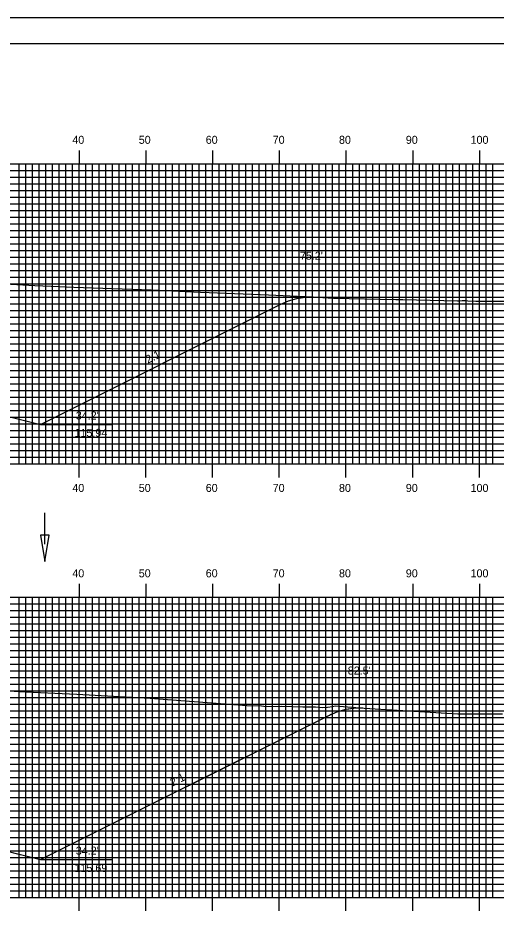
# Model space of a CAD drawing. Extents: x 1770448 to 1770792, y 442591 to 442811.
# Drawn here: x 1770644.9 to 1770716.5, y 442676.2 to 442810.5 of the extents above; entities that cross this region are included whole.
import ezdxf

# ---------------------------------------------------------------- set-up
doc = ezdxf.new("R2010")
doc.units = 0
for name, color, linetype in [('ANNOTATION', 7, 'Continuous'), ('BORDER', 7, 'Continuous'), ('D_Drainage_Ditch_Line', 7, 'Continuous'), ('D_Roadway_Centerline', 7, 'Continuous'), ('D_Roadway_SlopeLines', 7, 'Continuous'), ('D_Text_Standard', 7, 'Continuous'), ('H_V ANNOTATION', 7, 'Continuous'), ('MAJOR', 7, 'Continuous'), ('MINOR', 7, 'Continuous'), ('PDRAIN', 7, 'Continuous'), ('PLOT BOUNDARY', 7, 'Continuous'), ('S_Roadway_Centerline', 7, 'Continuous')]:
    doc.layers.add(name, color=color, linetype=linetype)

msp = doc.modelspace()

# ---------------------------------------------------------------- linework, layer by layer
at = {"layer": 'BORDER'}
msp.add_lwpolyline([(1770464.44, 442596.67), (1770784.44, 442596.67), (1770784.44, 442806.67), (1770464.44, 442806.67)], close=True, dxfattribs=at)
at = {"layer": 'D_Drainage_Ditch_Line'}
msp.add_line((1770648.9, 442731.66), (1770648.9, 442736.36), dxfattribs=at)
msp.add_lwpolyline([(1770649.56, 442732.97), (1770648.25, 442732.97), (1770648.9, 442729.03)], close=True, dxfattribs=at)
at = {"layer": 'D_Roadway_Centerline'}
for points in [[(1770644.22, 442750.6), (1770648.22, 442749.6), (1770684.19, 442767.59), (1770684.19, 442767.59), (1770685.44, 442768.13), (1770686.69, 442768.5), (1770687.64, 442768.65), (1770687.94, 442768.7), (1770689.19, 442768.73)], [(1770644.21, 442685.35), (1770646.62, 442684.75), (1770648.22, 442684.35), (1770664.41, 442692.45), (1770691.55, 442706.02), (1770691.73, 442706.1), (1770692.8, 442706.56), (1770694.05, 442706.91), (1770695.21, 442707.07), (1770695.3, 442707.09), (1770695.5, 442707.09), (1770696.55, 442707.09)]]:
    msp.add_lwpolyline(points, dxfattribs=at)
at = {"layer": 'D_Roadway_SlopeLines'}
for points in [[(1770648.22, 442749.6), (1770684.19, 442767.59), (1770685.44, 442768.13), (1770686.69, 442768.5), (1770687.94, 442768.7), (1770689.19, 442768.73)], [(1770634.04, 442753.15), (1770648.22, 442749.6)], [(1770648.22, 442684.35), (1770691.55, 442706.02), (1770692.8, 442706.56), (1770694.05, 442706.91), (1770695.3, 442707.09), (1770696.55, 442707.09)], [(1770634.04, 442687.9), (1770648.22, 442684.35)]]:
    msp.add_lwpolyline(points, dxfattribs=at)
at = {"layer": 'MAJOR'}
for p, q in [((1770654.04, 442790.67), (1770654.04, 442788.67)), ((1770664.04, 442790.67), (1770664.04, 442788.67)), ((1770674.04, 442790.67), (1770674.04, 442788.67)), ((1770684.04, 442790.67), (1770684.04, 442788.67)), ((1770694.04, 442790.67), (1770694.04, 442788.67)), ((1770704.04, 442790.67), (1770704.04, 442788.67)), ((1770714.04, 442790.67), (1770714.04, 442788.67)), ((1770474.04, 442788.67), (1770754.04, 442788.67)), ((1770474.04, 442788.67), (1770754.04, 442788.67)), ((1770654.04, 442743.67), (1770654.04, 442788.67)), ((1770664.04, 442743.67), (1770664.04, 442788.67)), ((1770674.04, 442743.67), (1770674.04, 442788.67)), ((1770684.04, 442743.67), (1770684.04, 442788.67)), ((1770694.04, 442743.67), (1770694.04, 442788.67)), ((1770704.04, 442743.67), (1770704.04, 442788.67)), ((1770714.04, 442743.67), (1770714.04, 442788.67)), ((1770474.04, 442783.67), (1770754.04, 442783.67)), ((1770474.04, 442778.67), (1770754.04, 442778.67)), ((1770474.04, 442773.67), (1770754.04, 442773.67)), ((1770474.04, 442768.67), (1770754.04, 442768.67)), ((1770474.04, 442763.67), (1770754.04, 442763.67)), ((1770474.04, 442758.67), (1770754.04, 442758.67)), ((1770474.04, 442753.67), (1770754.04, 442753.67)), ((1770474.04, 442748.67), (1770754.04, 442748.67)), ((1770474.04, 442743.67), (1770754.04, 442743.67)), ((1770474.04, 442743.67), (1770754.04, 442743.67)), ((1770654.04, 442741.66), (1770654.04, 442743.67)), ((1770664.04, 442741.66), (1770664.04, 442743.67)), ((1770674.04, 442741.66), (1770674.04, 442743.67)), ((1770684.04, 442741.66), (1770684.04, 442743.67)), ((1770694.04, 442741.66), (1770694.04, 442743.67)), ((1770704.04, 442741.66), (1770704.04, 442743.67)), ((1770714.04, 442741.66), (1770714.04, 442743.67)), ((1770654.04, 442725.67), (1770654.04, 442723.67)), ((1770664.04, 442725.67), (1770664.04, 442723.67)), ((1770674.04, 442725.67), (1770674.04, 442723.67)), ((1770684.04, 442725.67), (1770684.04, 442723.67)), ((1770694.04, 442725.67), (1770694.04, 442723.67)), ((1770704.04, 442725.67), (1770704.04, 442723.67)), ((1770714.04, 442725.67), (1770714.04, 442723.67)), ((1770474.04, 442723.67), (1770754.04, 442723.67)), ((1770474.04, 442723.67), (1770754.04, 442723.67)), ((1770654.04, 442678.67), (1770654.04, 442723.67)), ((1770664.04, 442678.67), (1770664.04, 442723.67)), ((1770674.04, 442678.67), (1770674.04, 442723.67)), ((1770684.04, 442678.67), (1770684.04, 442723.67)), ((1770694.04, 442678.67), (1770694.04, 442723.67)), ((1770704.04, 442678.67), (1770704.04, 442723.67)), ((1770714.04, 442678.67), (1770714.04, 442723.67)), ((1770474.04, 442718.67), (1770754.04, 442718.67)), ((1770474.04, 442713.67), (1770754.04, 442713.67)), ((1770474.04, 442708.67), (1770754.04, 442708.67)), ((1770474.04, 442703.67), (1770754.04, 442703.67)), ((1770474.04, 442698.67), (1770754.04, 442698.67)), ((1770474.04, 442693.67), (1770754.04, 442693.67)), ((1770474.04, 442688.67), (1770754.04, 442688.67)), ((1770474.04, 442683.67), (1770754.04, 442683.67)), ((1770474.04, 442678.67), (1770754.04, 442678.67)), ((1770474.04, 442678.67), (1770754.04, 442678.67)), ((1770654.04, 442676.66), (1770654.04, 442678.67)), ((1770664.04, 442676.66), (1770664.04, 442678.67)), ((1770674.04, 442676.66), (1770674.04, 442678.67)), ((1770684.04, 442676.66), (1770684.04, 442678.67)), ((1770694.04, 442676.66), (1770694.04, 442678.67)), ((1770704.04, 442676.66), (1770704.04, 442678.67)), ((1770714.04, 442676.66), (1770714.04, 442678.67))]:
    msp.add_line(p, q, dxfattribs=at)
at = {"layer": 'MINOR'}
for p, q in [((1770645.04, 442743.67), (1770645.04, 442788.67)), ((1770646.04, 442743.67), (1770646.04, 442788.67)), ((1770647.04, 442743.67), (1770647.04, 442788.67)), ((1770648.04, 442743.67), (1770648.04, 442788.67)), ((1770649.04, 442743.67), (1770649.04, 442788.67)), ((1770650.04, 442743.67), (1770650.04, 442788.67)), ((1770651.04, 442743.67), (1770651.04, 442788.67)), ((1770652.04, 442743.67), (1770652.04, 442788.67)), ((1770653.04, 442743.67), (1770653.04, 442788.67)), ((1770655.04, 442743.67), (1770655.04, 442788.67)), ((1770656.04, 442743.67), (1770656.04, 442788.67)), ((1770657.04, 442743.67), (1770657.04, 442788.67)), ((1770658.04, 442743.67), (1770658.04, 442788.67)), ((1770659.04, 442743.67), (1770659.04, 442788.67)), ((1770660.04, 442743.67), (1770660.04, 442788.67)), ((1770661.04, 442743.67), (1770661.04, 442788.67)), ((1770662.04, 442743.67), (1770662.04, 442788.67)), ((1770663.04, 442743.67), (1770663.04, 442788.67)), ((1770665.04, 442743.67), (1770665.04, 442788.67)), ((1770666.04, 442743.67), (1770666.04, 442788.67)), ((1770667.04, 442743.67), (1770667.04, 442788.67)), ((1770668.04, 442743.67), (1770668.04, 442788.67)), ((1770669.04, 442743.67), (1770669.04, 442788.67)), ((1770670.04, 442743.67), (1770670.04, 442788.67)), ((1770671.04, 442743.67), (1770671.04, 442788.67)), ((1770672.04, 442743.67), (1770672.04, 442788.67)), ((1770673.04, 442743.67), (1770673.04, 442788.67)), ((1770675.04, 442743.67), (1770675.04, 442788.67)), ((1770676.04, 442743.67), (1770676.04, 442788.67)), ((1770677.04, 442743.67), (1770677.04, 442788.67)), ((1770678.04, 442743.67), (1770678.04, 442788.67)), ((1770679.04, 442743.67), (1770679.04, 442788.67)), ((1770680.04, 442743.67), (1770680.04, 442788.67)), ((1770681.04, 442743.67), (1770681.04, 442788.67)), ((1770682.04, 442743.67), (1770682.04, 442788.67)), ((1770683.04, 442743.67), (1770683.04, 442788.67)), ((1770685.04, 442743.67), (1770685.04, 442788.67)), ((1770686.04, 442743.67), (1770686.04, 442788.67)), ((1770687.04, 442743.67), (1770687.04, 442788.67)), ((1770688.04, 442743.67), (1770688.04, 442788.67)), ((1770689.04, 442743.67), (1770689.04, 442788.67)), ((1770690.04, 442743.67), (1770690.04, 442788.67)), ((1770691.04, 442743.67), (1770691.04, 442788.67)), ((1770692.04, 442743.67), (1770692.04, 442788.67)), ((1770693.04, 442743.67), (1770693.04, 442788.67)), ((1770695.04, 442743.67), (1770695.04, 442788.67)), ((1770696.04, 442743.67), (1770696.04, 442788.67)), ((1770697.04, 442743.67), (1770697.04, 442788.67)), ((1770698.04, 442743.67), (1770698.04, 442788.67)), ((1770699.04, 442743.67), (1770699.04, 442788.67)), ((1770700.04, 442743.67), (1770700.04, 442788.67)), ((1770701.04, 442743.67), (1770701.04, 442788.67)), ((1770702.04, 442743.67), (1770702.04, 442788.67)), ((1770703.04, 442743.67), (1770703.04, 442788.67)), ((1770705.04, 442743.67), (1770705.04, 442788.67)), ((1770706.04, 442743.67), (1770706.04, 442788.67)), ((1770707.04, 442743.67), (1770707.04, 442788.67)), ((1770708.04, 442743.67), (1770708.04, 442788.67)), ((1770709.04, 442743.67), (1770709.04, 442788.67)), ((1770710.04, 442743.67), (1770710.04, 442788.67)), ((1770711.04, 442743.67), (1770711.04, 442788.67)), ((1770712.04, 442743.67), (1770712.04, 442788.67)), ((1770713.04, 442743.67), (1770713.04, 442788.67)), ((1770715.04, 442743.67), (1770715.04, 442788.67)), ((1770716.04, 442743.67), (1770716.04, 442788.67)), ((1770474.04, 442787.67), (1770754.04, 442787.67)), ((1770474.04, 442786.67), (1770754.04, 442786.67)), ((1770474.04, 442785.67), (1770754.04, 442785.67)), ((1770474.04, 442784.67), (1770754.04, 442784.67)), ((1770474.04, 442782.67), (1770754.04, 442782.67)), ((1770474.04, 442781.67), (1770754.04, 442781.67)), ((1770474.04, 442780.67), (1770754.04, 442780.67)), ((1770474.04, 442779.67), (1770754.04, 442779.67)), ((1770474.04, 442777.67), (1770754.04, 442777.67)), ((1770474.04, 442776.67), (1770754.04, 442776.67)), ((1770474.04, 442775.67), (1770754.04, 442775.67)), ((1770474.04, 442774.67), (1770754.04, 442774.67)), ((1770474.04, 442772.67), (1770754.04, 442772.67)), ((1770474.04, 442771.67), (1770754.04, 442771.67)), ((1770474.04, 442770.67), (1770754.04, 442770.67)), ((1770474.04, 442769.67), (1770754.04, 442769.67)), ((1770474.04, 442767.67), (1770754.04, 442767.67)), ((1770474.04, 442766.67), (1770754.04, 442766.67)), ((1770474.04, 442765.67), (1770754.04, 442765.67)), ((1770474.04, 442764.67), (1770754.04, 442764.67)), ((1770474.04, 442762.67), (1770754.04, 442762.67)), ((1770474.04, 442761.67), (1770754.04, 442761.67)), ((1770474.04, 442760.67), (1770754.04, 442760.67)), ((1770474.04, 442759.67), (1770754.04, 442759.67)), ((1770474.04, 442757.67), (1770754.04, 442757.67)), ((1770474.04, 442756.67), (1770754.04, 442756.67)), ((1770474.04, 442755.67), (1770754.04, 442755.67)), ((1770474.04, 442754.67), (1770754.04, 442754.67)), ((1770474.04, 442752.67), (1770754.04, 442752.67)), ((1770474.04, 442751.67), (1770754.04, 442751.67)), ((1770474.04, 442750.67), (1770754.04, 442750.67)), ((1770474.04, 442749.67), (1770754.04, 442749.67)), ((1770474.04, 442747.67), (1770754.04, 442747.67)), ((1770474.04, 442746.67), (1770754.04, 442746.67)), ((1770474.04, 442745.67), (1770754.04, 442745.67)), ((1770474.04, 442744.67), (1770754.04, 442744.67)), ((1770645.04, 442678.67), (1770645.04, 442723.67)), ((1770646.04, 442678.67), (1770646.04, 442723.67)), ((1770647.04, 442678.67), (1770647.04, 442723.67)), ((1770648.04, 442678.67), (1770648.04, 442723.67)), ((1770649.04, 442678.67), (1770649.04, 442723.67)), ((1770650.04, 442678.67), (1770650.04, 442723.67)), ((1770651.04, 442678.67), (1770651.04, 442723.67)), ((1770652.04, 442678.67), (1770652.04, 442723.67)), ((1770653.04, 442678.67), (1770653.04, 442723.67)), ((1770655.04, 442678.67), (1770655.04, 442723.67)), ((1770656.04, 442678.67), (1770656.04, 442723.67)), ((1770657.04, 442678.67), (1770657.04, 442723.67)), ((1770658.04, 442678.67), (1770658.04, 442723.67)), ((1770659.04, 442678.67), (1770659.04, 442723.67)), ((1770660.04, 442678.67), (1770660.04, 442723.67)), ((1770661.04, 442678.67), (1770661.04, 442723.67)), ((1770662.04, 442678.67), (1770662.04, 442723.67)), ((1770663.04, 442678.67), (1770663.04, 442723.67)), ((1770665.04, 442678.67), (1770665.04, 442723.67)), ((1770666.04, 442678.67), (1770666.04, 442723.67)), ((1770667.04, 442678.67), (1770667.04, 442723.67)), ((1770668.04, 442678.67), (1770668.04, 442723.67)), ((1770669.04, 442678.67), (1770669.04, 442723.67)), ((1770670.04, 442678.67), (1770670.04, 442723.67)), ((1770671.04, 442678.67), (1770671.04, 442723.67)), ((1770672.04, 442678.67), (1770672.04, 442723.67)), ((1770673.04, 442678.67), (1770673.04, 442723.67)), ((1770675.04, 442678.67), (1770675.04, 442723.67)), ((1770676.04, 442678.67), (1770676.04, 442723.67)), ((1770677.04, 442678.67), (1770677.04, 442723.67)), ((1770678.04, 442678.67), (1770678.04, 442723.67)), ((1770679.04, 442678.67), (1770679.04, 442723.67)), ((1770680.04, 442678.67), (1770680.04, 442723.67)), ((1770681.04, 442678.67), (1770681.04, 442723.67)), ((1770682.04, 442678.67), (1770682.04, 442723.67)), ((1770683.04, 442678.67), (1770683.04, 442723.67)), ((1770685.04, 442678.67), (1770685.04, 442723.67)), ((1770686.04, 442678.67), (1770686.04, 442723.67)), ((1770687.04, 442678.67), (1770687.04, 442723.67)), ((1770688.04, 442678.67), (1770688.04, 442723.67)), ((1770689.04, 442678.67), (1770689.04, 442723.67)), ((1770690.04, 442678.67), (1770690.04, 442723.67)), ((1770691.04, 442678.67), (1770691.04, 442723.67)), ((1770692.04, 442678.67), (1770692.04, 442723.67)), ((1770693.04, 442678.67), (1770693.04, 442723.67)), ((1770695.04, 442678.67), (1770695.04, 442723.67)), ((1770696.04, 442678.67), (1770696.04, 442723.67)), ((1770697.04, 442678.67), (1770697.04, 442723.67)), ((1770698.04, 442678.67), (1770698.04, 442723.67)), ((1770699.04, 442678.67), (1770699.04, 442723.67)), ((1770700.04, 442678.67), (1770700.04, 442723.67)), ((1770701.04, 442678.67), (1770701.04, 442723.67)), ((1770702.04, 442678.67), (1770702.04, 442723.67)), ((1770703.04, 442678.67), (1770703.04, 442723.67)), ((1770705.04, 442678.67), (1770705.04, 442723.67)), ((1770706.04, 442678.67), (1770706.04, 442723.67)), ((1770707.04, 442678.67), (1770707.04, 442723.67)), ((1770708.04, 442678.67), (1770708.04, 442723.67)), ((1770709.04, 442678.67), (1770709.04, 442723.67)), ((1770710.04, 442678.67), (1770710.04, 442723.67)), ((1770711.04, 442678.67), (1770711.04, 442723.67)), ((1770712.04, 442678.67), (1770712.04, 442723.67)), ((1770713.04, 442678.67), (1770713.04, 442723.67)), ((1770715.04, 442678.67), (1770715.04, 442723.67)), ((1770716.04, 442678.67), (1770716.04, 442723.67)), ((1770474.04, 442722.67), (1770754.04, 442722.67)), ((1770474.04, 442721.67), (1770754.04, 442721.67)), ((1770474.04, 442720.67), (1770754.04, 442720.67)), ((1770474.04, 442719.67), (1770754.04, 442719.67)), ((1770474.04, 442717.67), (1770754.04, 442717.67)), ((1770474.04, 442716.67), (1770754.04, 442716.67)), ((1770474.04, 442715.67), (1770754.04, 442715.67)), ((1770474.04, 442714.67), (1770754.04, 442714.67)), ((1770474.04, 442712.67), (1770754.04, 442712.67)), ((1770474.04, 442711.67), (1770754.04, 442711.67)), ((1770474.04, 442710.67), (1770754.04, 442710.67)), ((1770474.04, 442709.67), (1770754.04, 442709.67)), ((1770474.04, 442707.67), (1770754.04, 442707.67)), ((1770474.04, 442706.67), (1770754.04, 442706.67)), ((1770474.04, 442705.67), (1770754.04, 442705.67)), ((1770474.04, 442704.67), (1770754.04, 442704.67)), ((1770474.04, 442702.67), (1770754.04, 442702.67)), ((1770474.04, 442701.67), (1770754.04, 442701.67)), ((1770474.04, 442700.67), (1770754.04, 442700.67)), ((1770474.04, 442699.67), (1770754.04, 442699.67)), ((1770474.04, 442697.67), (1770754.04, 442697.67)), ((1770474.04, 442696.67), (1770754.04, 442696.67)), ((1770474.04, 442695.67), (1770754.04, 442695.67)), ((1770474.04, 442694.67), (1770754.04, 442694.67)), ((1770474.04, 442692.67), (1770754.04, 442692.67)), ((1770474.04, 442691.67), (1770754.04, 442691.67)), ((1770474.04, 442690.67), (1770754.04, 442690.67)), ((1770474.04, 442689.67), (1770754.04, 442689.67)), ((1770474.04, 442687.67), (1770754.04, 442687.67)), ((1770474.04, 442686.67), (1770754.04, 442686.67)), ((1770474.04, 442685.67), (1770754.04, 442685.67)), ((1770474.04, 442684.67), (1770754.04, 442684.67)), ((1770474.04, 442682.67), (1770754.04, 442682.67)), ((1770474.04, 442681.67), (1770754.04, 442681.67)), ((1770474.04, 442680.67), (1770754.04, 442680.67)), ((1770474.04, 442679.67), (1770754.04, 442679.67))]:
    msp.add_line(p, q, dxfattribs=at)
at = {"layer": 'PDRAIN'}
for p, q in [((1770648.22, 442749.6), (1770658.99, 442749.6)), ((1770648.22, 442684.35), (1770658.99, 442684.35))]:
    msp.add_line(p, q, dxfattribs=at)
at = {"layer": 'PLOT BOUNDARY'}
msp.add_lwpolyline([(1770448.25, 442590.55), (1770788.25, 442590.55), (1770788.25, 442810.55), (1770448.25, 442810.55)], close=True, dxfattribs=at)
at = {"layer": 'S_Roadway_Centerline'}
for points in [[(1770632.95, 442771.24), (1770647.41, 442770.43), (1770651.01, 442770.28), (1770653.21, 442770.17), (1770664.83, 442769.78), (1770672.2, 442769.43), (1770676.05, 442769.26), (1770682.44, 442769.03), (1770688.99, 442768.74), (1770692.16, 442768.52), (1770701.49, 442768.35), (1770702.57, 442768.34), (1770710.75, 442768.14), (1770711.11, 442768.14), (1770711.48, 442768.17), (1770711.76, 442768.17), (1770712.08, 442768.16), (1770712.32, 442768.14), (1770713.52, 442768.09), (1770723.83, 442768.1), (1770730.53, 442768.04), (1770743.12, 442767.64), (1770750.6, 442767.55), (1770754.04, 442767.48)], [(1770642.29, 442709.74), (1770644.95, 442709.56), (1770653.7, 442709.16), (1770664.68, 442708.55), (1770665.32, 442708.5), (1770665.96, 442708.46), (1770679.16, 442707.45), (1770681.39, 442707.38), (1770682.06, 442707.29), (1770684.4, 442707.35), (1770685.92, 442707.32), (1770687.59, 442707.26), (1770689.49, 442707.24), (1770690.56, 442707.17), (1770691.27, 442707.19), (1770692.04, 442707.32), (1770692.41, 442707.39), (1770696.76, 442707.07), (1770710.81, 442706.18), (1770717.51, 442706.19)]]:
    msp.add_lwpolyline(points, dxfattribs=at)

# ---------------------------------------------------------------- texts
at = {"layer": 'ANNOTATION'}
for rotation, p in [(26.5648, (1770664.35, 442758.7)), (26.5654, (1770668.03, 442695.3))]:
    msp.add_text('2:1', height=1.2, rotation=rotation, dxfattribs=at).set_placement(p)
for s, p in [("34.2'", (1770653.53, 442750.33)), ('115.94', (1770653.34, 442747.73)), ("34.2'", (1770653.53, 442685.08)), ('115.69', (1770653.34, 442682.48))]:
    msp.add_text(s, height=1.2, dxfattribs=at).set_placement(p)
at = {"layer": 'D_Text_Standard'}
for s, p in [("75.2'", (1770687.13, 442774.29)), ("82.5'", (1770694.31, 442712.09))]:
    msp.add_text(s, height=1.2, dxfattribs=at).set_placement(p)
at = {"layer": 'H_V ANNOTATION'}
for s, p in [('40', (1770653.01, 442791.67)), ('50', (1770662.97, 442791.67)), ('60', (1770673.01, 442791.67)), ('70', (1770683.05, 442791.67)), ('80', (1770692.99, 442791.67)), ('90', (1770703.01, 442791.67)), ('100', (1770712.72, 442791.67)), ('40', (1770653.01, 442739.47)), ('50', (1770662.97, 442739.47)), ('60', (1770673.01, 442739.47)), ('70', (1770683.05, 442739.47)), ('80', (1770692.99, 442739.47)), ('90', (1770703.01, 442739.47)), ('100', (1770712.72, 442739.47)), ('40', (1770653.01, 442726.67)), ('50', (1770662.97, 442726.67)), ('60', (1770673.01, 442726.67)), ('70', (1770683.05, 442726.67)), ('80', (1770692.99, 442726.67)), ('90', (1770703.01, 442726.67)), ('100', (1770712.72, 442726.67))]:
    msp.add_text(s, height=1.2, dxfattribs=at).set_placement(p)

doc.saveas('drawing.dxf')
